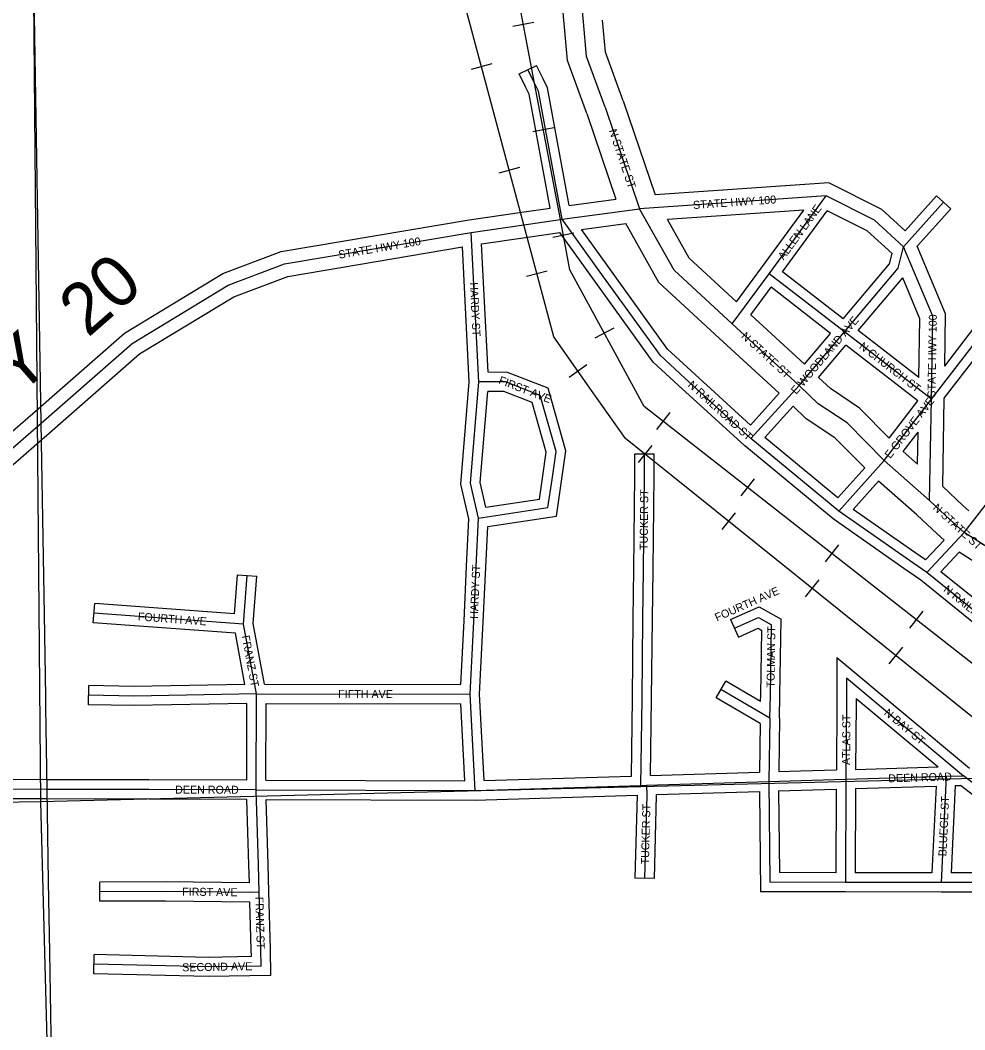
# Model space of a CAD drawing. Extents: x 457167 to 656239, y 1787309 to 1969297.
# Drawn here: x 569552 to 572503, y 1865532 to 1868685 of the extents above; entities that cross this region are included whole.
import ezdxf

# ---------------------------------------------------------------- set-up
doc = ezdxf.new("R2010")
doc.units = 0
for name, color, linetype in [('Level 1', 7, 'Continuous'), ('Level 13', 7, 'Continuous'), ('Level 14', 7, 'Continuous'), ('Level 22', 7, 'Continuous'), ('Level 23', 7, 'Continuous'), ('Level 28', 7, 'Continuous'), ('Level 31', 7, 'Continuous'), ('Level 32', 7, 'Continuous'), ('Level 34', 7, 'Continuous'), ('Level 37', 7, 'Continuous'), ('Level 8', 7, 'Continuous')]:
    doc.layers.add(name, color=color, linetype=linetype)

msp = doc.modelspace()

# ---------------------------------------------------------------- linework, layer by layer
at = {"layer": 'Level 1'}
for p, q in [((569570.685, 1871499.854), (569615.691, 1866243.956)), ((574895.419, 1866376.943), (569615.691, 1866243.956)), ((569615.691, 1866243.956), (564358.417, 1866182.997)), ((569615.691, 1866243.956), (569751.086, 1861047.655))]:
    msp.add_line(p, q, dxfattribs=at)
at = {"layer": 'Level 13'}
for p, q in [((571311.617, 1868679.365), (571287.401, 1868943.418)), ((571379.106, 1868413.031), (571486.576, 1868096.061)), ((571594.65, 1867903.816), (571486.576, 1868096.061)), ((571776.29, 1867736.496), (571594.65, 1867903.816)), ((571985.241, 1867544.389), (571776.29, 1867736.496)), ((572393.025, 1867184.926), (572251.381, 1867310.336)), ((572457.488, 1867124.781), (572393.025, 1867184.926)), ((572500.994, 1867084.684), (572457.488, 1867124.781)), ((572817.176, 1866883.612), (572500.994, 1867084.684))]:
    msp.add_line(p, q, dxfattribs=at)
for points in [[(571379.106, 1868413.031), (571321.236, 1868571.707), (571311.617, 1868679.365)], [(572251.381, 1867310.336), (572135.176, 1867427.324), (572045.306, 1867487.276), (571985.241, 1867544.389)]]:
    msp.add_lwpolyline(points, dxfattribs=at)
at = {"layer": 'Level 14'}
for p, q in [((571251.867, 1868673.884), (571227.65, 1868937.937)), ((571435.711, 1868432.946), (571535.205, 1868139.5)), ((571322.503, 1868393.115), (571412.934, 1868126.401)), ((571547.006, 1867866.126), (571443.721, 1868049.854)), ((571642.295, 1867941.506), (571574.549, 1868062.015)), ((571789.897, 1867805.54), (571642.296, 1867941.506)), ((571735.637, 1867692.366), (571547.006, 1867866.126)), ((572001.992, 1867610.495), (571834.307, 1867764.662)), ((571922.916, 1867520.183), (571735.68, 1867692.326)), ((572354.991, 1867298.74), (572310.564, 1867338.075)), ((572352.666, 1867140.521), (572233.771, 1867245.786)), ((572498.152, 1867168.901), (572433.795, 1867228.949)), ((572515.666, 1867152.761), (572498.152, 1867168.901)), ((572416.556, 1867080.91), (572352.666, 1867140.52)), ((572437.886, 1867061.249), (572416.825, 1867080.661)), ((572753.867, 1866852.766), (572484.986, 1867023.758))]:
    msp.add_line(p, q, dxfattribs=at)
for points in [[(571322.503, 1868393.116), (571262.172, 1868558.536), (571251.855, 1868674.025)], [(571435.711, 1868432.945), (571380.299, 1868584.879), (571371.38, 1868684.705)], [(572266.956, 1867379.796), (572173.493, 1867473.889), (572082.904, 1867534.321), (572045.901, 1867569.505)], [(572190.067, 1867286.921), (572096.86, 1867380.759), (572007.706, 1867440.231), (571966.739, 1867479.186)]]:
    msp.add_lwpolyline(points, dxfattribs=at)
at = {"layer": 'Level 22'}
for p, q in [((572070.271, 1868136.193), (571486.576, 1868096.061)), ((571244.976, 1868063.157), (571486.576, 1868096.061)), ((570961.354, 1868022.351), (571125.289, 1868045.976)), ((571125.289, 1868045.976), (571239.565, 1868062.442)), ((571239.565, 1868062.442), (571244.976, 1868063.157)), ((572393.025, 1867184.926), (572398.511, 1867501.639)), ((568581.391, 1866522.794), (569617.736, 1867426.909))]:
    msp.add_line(p, q, dxfattribs=at)
for points in [[(572311.756, 1867977.103), (572220.298, 1868060.582), (572070.271, 1868136.193)], [(569617.736, 1867426.909), (569901.528, 1867674.976), (570202.348, 1867857.552), (570377.52, 1867923.693), (570961.354, 1868022.351)], [(572398.511, 1867501.639), (572402.913, 1867760.172), (572311.756, 1867977.103)]]:
    msp.add_lwpolyline(points, dxfattribs=at)
at = {"layer": 'Level 23'}
for p, q in [((572078.476, 1868176.851), (571535.206, 1868139.499)), ((571119.585, 1868085.568), (571207.957, 1868098.301)), ((571267.445, 1868106.586), (571412.935, 1868126.401)), ((570955.168, 1868061.873), (571119.583, 1868085.568)), ((572000.041, 1868091.269), (571574.549, 1868062.015)), ((571305.166, 1868030.983), (571443.72, 1868049.854)), ((570993.216, 1867986.528), (571130.995, 1868006.384)), ((571130.993, 1868006.384), (571237.83, 1868021.778)), ((572433.795, 1867228.949), (572438.568, 1867504.474)), ((568567.431, 1866563.696), (569591.441, 1867457.051)), ((568607.686, 1866492.651), (569644.033, 1867396.766)), ((572354.991, 1867298.74), (572356.711, 1867398.078))]:
    msp.add_line(p, q, dxfattribs=at)
for points in [[(572316.315, 1868027.099), (572243.207, 1868093.831), (572078.476, 1868176.851)], [(572275.451, 1867956.083), (572197.389, 1868027.334), (572073.423, 1868089.811)], [(569591.411, 1867457.026), (569877.811, 1867707.374), (570184.757, 1867893.667), (570367.024, 1867962.486), (570955.168, 1868061.874)], [(569644.062, 1867396.792), (569925.245, 1867642.579), (570219.939, 1867821.436), (570388.016, 1867884.899), (570933.617, 1867977.096)], [(572440.28, 1867605.007), (572443.051, 1867767.908), (572354.163, 1867979.439)], [(572359.661, 1867569.536), (572362.775, 1867752.436), (572308.942, 1867880.546)]]:
    msp.add_lwpolyline(points, dxfattribs=at)
at = {"layer": 'Level 31'}
for p, q in [((571158.757, 1868488.078), (571137.852, 1868530.308)), ((571891.84, 1867893.326), (572070.271, 1868136.193)), ((572311.756, 1867977.103), (572436.491, 1868116.095)), ((571361.076, 1867902.166), (571244.976, 1868063.157)), ((570985.104, 1867555.391), (570961.354, 1868022.351)), ((571776.29, 1867736.496), (571891.84, 1867893.326)), ((572126.908, 1867711.341), (571891.84, 1867893.326)), ((572398.511, 1867501.639), (572588.406, 1867748.119)), ((571985.241, 1867544.389), (572126.908, 1867711.341)), ((572398.511, 1867501.639), (572126.908, 1867711.341)), ((571834.984, 1867378.185), (571628.252, 1867567.38)), ((570959.239, 1867238.725), (570985.104, 1867555.391)), ((571834.984, 1867378.185), (571985.241, 1867544.389)), ((572251.381, 1867310.336), (572398.511, 1867501.639)), ((572109.415, 1867152.111), (571834.984, 1867378.185)), ((571502.181, 1867263.305), (571502.653, 1867330.94)), ((572109.415, 1867152.111), (572251.381, 1867310.336)), ((572500.994, 1867084.684), (572664.719, 1867296.679)), ((571498.966, 1866969.496), (571502.181, 1867263.305)), ((570983.812, 1867130.306), (570959.239, 1867238.725)), ((572329.595, 1866997.797), (572109.415, 1867152.111)), ((570976.781, 1866978.323), (570983.812, 1867130.306)), ((572383.925, 1866959.857), (572500.994, 1867084.684)), ((572383.925, 1866959.857), (572329.595, 1866997.797)), ((570968.753, 1866807.796), (570976.781, 1866978.323)), ((571497.341, 1866814.956), (571498.966, 1866969.496)), ((570249.543, 1866798.905), (570261.033, 1866951.241)), ((572683.466, 1866717.368), (572383.925, 1866959.857)), ((570249.543, 1866798.905), (569782.786, 1866833.439)), ((570957.411, 1866580.188), (570968.753, 1866807.796)), ((571494.549, 1866566.963), (571497.341, 1866814.956)), ((570290.411, 1866581.721), (570249.543, 1866798.905)), ((571895.54, 1866577.69), (571898.901, 1866796.953)), ((572133.376, 1866630.971), (572133.197, 1866551.698)), ((572133.376, 1866630.971), (572498.968, 1866325.786)), ((571894.104, 1866505.694), (571741.238, 1866594.766)), ((569906.93, 1866574.607), (569765.962, 1866577.48)), ((570290.411, 1866581.721), (569906.93, 1866574.607)), ((570289.718, 1866281.725), (570290.411, 1866581.721)), ((570290.411, 1866581.721), (570957.411, 1866580.188)), ((570973.271, 1866279.791), (570957.411, 1866580.188)), ((571491.066, 1866295.336), (571494.549, 1866566.963)), ((571894.104, 1866505.694), (571895.54, 1866577.69)), ((572133.197, 1866551.698), (572131.706, 1866314.612)), ((571894.104, 1866505.694), (571891.109, 1866307.52)), ((571508.571, 1866296.024), (571891.109, 1866307.52)), ((571891.109, 1866307.52), (571990.403, 1866310.568)), ((571891.109, 1866307.52), (571894.216, 1865993.334)), ((571990.403, 1866310.568), (572131.706, 1866314.612)), ((572131.706, 1866314.612), (572129.706, 1865992.801)), ((572131.706, 1866314.612), (572444.547, 1866324.09)), ((572444.547, 1866324.09), (572428.844, 1865992.491)), ((572444.547, 1866324.09), (572498.968, 1866325.786)), ((572841.107, 1866060.656), (572498.968, 1866325.786)), ((569636.396, 1866283.237), (569470.181, 1866283.63)), ((569953.669, 1866282.501), (569636.396, 1866283.237)), ((570289.718, 1866281.725), (569953.669, 1866282.501)), ((570289.718, 1866281.725), (570973.271, 1866279.791)), ((570296.497, 1866047.892), (570289.718, 1866281.725)), ((570973.271, 1866279.791), (571491.066, 1866295.336)), ((571491.066, 1866295.336), (571508.571, 1866296.024)), ((570298.845, 1865962.069), (570296.497, 1866047.892)), ((572129.706, 1865992.801), (571894.216, 1865993.334)), ((572428.844, 1865992.491), (572129.706, 1865992.801)), ((572841.59, 1865991.929), (572428.844, 1865992.491)), ((570005.758, 1865964.565), (569801.132, 1865963.585)), ((570303.842, 1865783.514), (570298.845, 1865962.069)), ((570304.995, 1865731.511), (570303.842, 1865783.514)), ((570139.156, 1865728.676), (569783.104, 1865737.446)), ((570304.995, 1865731.511), (570139.156, 1865728.676))]:
    msp.add_line(p, q, dxfattribs=at)
for points in [[(571244.976, 1868063.157), (571170.793, 1868463.687), (571158.757, 1868488.078)], [(572126.908, 1867711.341), (572294.739, 1867910.233), (572311.756, 1867977.103)], [(571628.252, 1867567.38), (571552.039, 1867637.371), (571361.076, 1867902.166)], [(571176.576, 1867513.136), (571068.477, 1867555.2), (570985.104, 1867555.391)], [(571213.524, 1867250.144), (571226.136, 1867338.115), (571176.576, 1867513.136)], [(570983.812, 1867130.306), (571200.596, 1867162.901), (571213.524, 1867250.144)], [(571783.361, 1866786.306), (571858.538, 1866819.59), (571898.901, 1866796.953)], [(571508.571, 1866296.024), (571509.134, 1866263.66), (571502.5, 1866005.495)], [(570298.845, 1865962.069), (570268.611, 1865961.412), (570005.758, 1865964.565)]]:
    msp.add_lwpolyline(points, dxfattribs=at)
at = {"layer": 'Level 32'}
for p, q in [((571110.966, 1868516.998), (571164.739, 1868543.616)), ((571185.644, 1868501.387), (571164.739, 1868543.616)), ((571131.871, 1868474.769), (571110.966, 1868516.998)), ((572316.315, 1868027.099), (572414.163, 1868136.131)), ((572414.163, 1868136.131), (572458.819, 1868096.057)), ((572354.163, 1867979.44), (572458.819, 1868096.057)), ((571867.664, 1867911.087), (572000.041, 1868091.268)), ((571933.339, 1867899.138), (572073.423, 1868089.811)), ((571336.743, 1867884.618), (571237.83, 1868021.778)), ((571385.41, 1867919.714), (571305.166, 1868030.983)), ((570955.042, 1867555.851), (570933.617, 1867977.096)), ((571013.622, 1867585.326), (570993.216, 1867986.529)), ((571789.897, 1867805.54), (571867.688, 1867911.121)), ((572122.53, 1867752.67), (571933.339, 1867899.137)), ((572170.044, 1867715.939), (572308.942, 1867880.546)), ((571834.306, 1867764.662), (571897.769, 1867850.795)), ((572083.732, 1867706.826), (571897.769, 1867850.795)), ((572440.28, 1867605.007), (572564.641, 1867766.428)), ((572438.568, 1867504.473), (572612.172, 1867729.81)), ((572001.991, 1867610.495), (572083.732, 1867706.826)), ((572359.661, 1867569.536), (572170.044, 1867715.938)), ((572045.901, 1867569.506), (572131.25, 1867670.086)), ((572356.476, 1867496.192), (572131.249, 1867670.086)), ((571832.971, 1867420.692), (571648.507, 1867589.511)), ((570928.965, 1867236.581), (570955.042, 1867555.851)), ((571815.306, 1867355.526), (571607.999, 1867545.248)), ((570989.516, 1867240.868), (571012.75, 1867525.326)), ((571832.972, 1867420.692), (571922.917, 1867520.183)), ((571878.304, 1867381.366), (571966.739, 1867479.186)), ((572266.956, 1867379.796), (572356.476, 1867496.192)), ((572106.293, 1867193.551), (571878.305, 1867381.366)), ((572310.564, 1867338.075), (572356.711, 1867398.078)), ((572091.241, 1867128.213), (571815.306, 1867355.525)), ((571472.181, 1867263.513), (571472.654, 1867331.148)), ((571472.654, 1867331.148), (571532.654, 1867330.73)), ((571532.182, 1867263.095), (571532.654, 1867330.73)), ((572106.292, 1867193.552), (572190.067, 1867286.921)), ((571468.969, 1866969.824), (571472.183, 1867263.632)), ((571528.966, 1866969.167), (571532.181, 1867262.976)), ((572154.341, 1867157.258), (572233.772, 1867245.786)), ((570953.656, 1867127.634), (570928.965, 1867236.58)), ((571006.911, 1867164.116), (570989.516, 1867240.868)), ((572346.771, 1867022.394), (572154.341, 1867157.258)), ((570946.813, 1866979.709), (570953.656, 1867127.635)), ((572312.377, 1866973.23), (572091.241, 1867128.212)), ((571006.75, 1866976.936), (571012.643, 1867104.301)), ((572379.81, 1866999.323), (572437.887, 1867061.249)), ((572379.81, 1866999.323), (572346.771, 1867022.394)), ((572427.882, 1866962.871), (572484.986, 1867023.758)), ((570938.786, 1866809.207), (570946.814, 1866979.733)), ((570998.721, 1866806.386), (571006.749, 1866976.911)), ((571467.342, 1866815.27), (571468.968, 1866969.811)), ((571527.341, 1866814.64), (571528.966, 1866969.181)), ((572365.876, 1866935.87), (572312.419, 1866973.201)), ((572678.951, 1866759.621), (572427.882, 1866962.871)), ((570221.881, 1866831.033), (570231.118, 1866953.497)), ((570231.118, 1866953.497), (570290.95, 1866948.984)), ((570279.756, 1866800.577), (570290.95, 1866948.984)), ((572664.341, 1866694.255), (572365.876, 1866935.87)), ((569780.573, 1866803.521), (569785, 1866863.357)), ((570221.881, 1866831.032), (569785, 1866863.357)), ((570224.326, 1866770.687), (569780.573, 1866803.521)), ((570928.872, 1866610.253), (570938.79, 1866809.289)), ((570987.452, 1866580.232), (570998.717, 1866806.304)), ((571464.551, 1866567.301), (571467.343, 1866815.292)), ((571524.548, 1866566.625), (571527.34, 1866814.617)), ((571771.216, 1866813.738), (571795.506, 1866758.874)), ((571925.537, 1866577.23), (571929.173, 1866814.371)), ((570315.304, 1866611.663), (570279.756, 1866800.577)), ((571865.546, 1866578.288), (571868.631, 1866779.533)), ((570254.364, 1866611.057), (570224.326, 1866770.687)), ((572103.521, 1866694.971), (572103.197, 1866551.766)), ((572103.521, 1866694.971), (572517.776, 1866349.165)), ((571726.135, 1866568.846), (571756.342, 1866620.687)), ((571865.127, 1866557.299), (571756.342, 1866620.687)), ((569765.351, 1866547.486), (569766.574, 1866607.474)), ((569906.958, 1866604.613), (569766.574, 1866607.474)), ((570254.364, 1866611.056), (569906.958, 1866604.612)), ((570315.304, 1866611.663), (570928.873, 1866610.253)), ((570260.34, 1866551.156), (569906.903, 1866544.601)), ((570259.788, 1866311.794), (570260.34, 1866551.156)), ((570319.788, 1866311.64), (570320.342, 1866551.651)), ((570320.342, 1866551.651), (570928.951, 1866550.252)), ((571001.684, 1866310.656), (570987.452, 1866580.232)), ((571461.437, 1866324.46), (571464.551, 1866567.347)), ((571521.47, 1866326.425), (571524.548, 1866566.578)), ((571863.843, 1866488.605), (571726.135, 1866568.846)), ((571865.128, 1866557.3), (571865.546, 1866578.288)), ((571924.101, 1866505.24), (571925.535, 1866577.091)), ((572103.197, 1866551.886), (572101.889, 1866343.771)), ((572163.197, 1866551.51), (572161.903, 1866345.541)), ((572163.232, 1866566.967), (572163.197, 1866551.631)), ((572163.233, 1866566.967), (572419.152, 1866353.334)), ((569906.903, 1866544.601), (569765.351, 1866547.486)), ((570941.641, 1866309.88), (570928.951, 1866550.252)), ((571863.843, 1866488.605), (571861.546, 1866336.645)), ((571924.101, 1866505.24), (571921.581, 1866338.469)), ((571521.47, 1866326.425), (571861.546, 1866336.644)), ((571921.581, 1866338.469), (571989.483, 1866340.554)), ((571989.546, 1866340.556), (572101.89, 1866343.771)), ((572161.903, 1866345.541), (572419.152, 1866353.334)), ((569636.466, 1866313.237), (569511.154, 1866313.528)), ((569953.739, 1866312.501), (569636.465, 1866313.237)), ((570259.787, 1866311.793), (569953.739, 1866312.501)), ((570319.788, 1866311.639), (570941.641, 1866309.88)), ((571001.685, 1866310.656), (571461.438, 1866324.46)), ((571539.083, 1866266.926), (571861.413, 1866276.613)), ((571861.413, 1866276.612), (571864.51, 1865963.4)), ((571921.4, 1866278.434), (571991.325, 1866280.581)), ((571921.4, 1866278.434), (571923.922, 1866023.266)), ((571991.262, 1866280.579), (572101.515, 1866283.734)), ((572101.515, 1866283.734), (572099.893, 1866022.869)), ((572161.527, 1866285.501), (572159.895, 1866022.77)), ((572161.527, 1866285.501), (572413.047, 1866293.121)), ((572413.048, 1866293.121), (572400.233, 1866022.521)), ((572473.203, 1866294.966), (572460.297, 1866022.448)), ((572473.203, 1866294.967), (572489.121, 1866295.462)), ((572811.211, 1866045.87), (572489.121, 1866295.463)), ((569636.326, 1866253.237), (569480.076, 1866253.6)), ((569953.6, 1866252.501), (569636.326, 1866253.237)), ((570260.574, 1866251.791), (569953.6, 1866252.501)), ((570266.51, 1866047.022), (570260.574, 1866251.791)), ((570320.604, 1866251.636), (570973.68, 1866249.789)), ((570326.485, 1866048.761), (570320.604, 1866251.636)), ((570973.68, 1866249.789), (571479.156, 1866264.966)), ((571479.156, 1866264.966), (571472.509, 1866006.266)), ((570268.031, 1865991.421), (570266.508, 1866047.071)), ((570328.834, 1865962.889), (570326.486, 1866048.711)), ((572099.893, 1866022.868), (571923.922, 1866023.266)), ((572400.232, 1866022.521), (572159.894, 1866022.769)), ((572811.378, 1866021.969), (572460.297, 1866022.448)), ((570005.875, 1865994.566), (569800.99, 1865993.584)), ((569801.276, 1865933.584), (569800.99, 1865993.584)), ((570268.031, 1865991.421), (570005.875, 1865994.566)), ((571532.49, 1866004.725), (571472.509, 1866006.266)), ((570333.831, 1865784.353), (570328.833, 1865962.908)), ((572129.639, 1865962.801), (571864.51, 1865963.4)), ((572428.813, 1865962.491), (572129.676, 1865962.801)), ((572871.803, 1865961.887), (572428.803, 1865962.491)), ((570005.691, 1865934.563), (569801.276, 1865933.584)), ((570273.854, 1865782.675), (570269.691, 1865931.427)), ((569782.366, 1865707.454), (569783.842, 1865767.437)), ((570139.292, 1865758.682), (569783.842, 1865767.437)), ((570274.334, 1865760.991), (570273.849, 1865782.849)), ((570335.657, 1865702.03), (570333.836, 1865784.179)), ((570274.335, 1865760.991), (570139.292, 1865758.682)), ((570139.031, 1865698.669), (569782.366, 1865707.454)), ((570335.656, 1865702.031), (570139.031, 1865698.669))]:
    msp.add_line(p, q, dxfattribs=at)
for points in [[(571207.957, 1868098.301), (571142.051, 1868454.138), (571131.854, 1868474.803)], [(571267.445, 1868106.586), (571199.536, 1868473.237), (571185.66, 1868501.354)], [(572122.53, 1867752.67), (572267.366, 1867924.312), (572275.45, 1867956.083)], [(571648.546, 1867589.476), (571574.583, 1867657.399), (571385.409, 1867919.715)], [(571607.96, 1867545.283), (571529.495, 1867617.342), (571336.743, 1867884.618)], [(571201.373, 1867535.678), (571074.142, 1867585.187), (571013.622, 1867585.325)], [(571243.221, 1867245.886), (571256.736, 1867340.161), (571201.373, 1867535.678)], [(571151.779, 1867490.591), (571062.812, 1867525.213), (571012.75, 1867525.326)], [(571183.827, 1867254.401), (571195.536, 1867336.068), (571151.779, 1867490.591)], [(571006.911, 1867164.115), (571174.175, 1867189.266), (571183.848, 1867254.541)], [(571012.643, 1867104.302), (571227.018, 1867136.536), (571243.201, 1867245.746)], [(571771.216, 1866813.738), (571860.12, 1866853.1), (571929.172, 1866814.371)], [(571795.506, 1866758.874), (571856.956, 1866786.08), (571868.631, 1866779.533)], [(571539.083, 1866266.926), (571539.141, 1866263.535), (571532.49, 1866004.725)], [(570269.69, 1865931.427), (570268.756, 1865931.407), (570005.691, 1865934.563)]]:
    msp.add_lwpolyline(points, dxfattribs=at)
at = {"layer": 'Level 37'}
for p, q in [((571157.119, 1868677.292), (571090.958, 1868664.736)), ((571025.933, 1868548.426), (570960.871, 1868531.047)), ((571219.566, 1868348.311), (571153.404, 1868335.75)), ((571112.346, 1868224.909), (571047.285, 1868207.531)), ((571282.013, 1868019.319), (571215.85, 1868006.772)), ((571198.758, 1867901.391), (571133.696, 1867884.014)), ((571406.621, 1867723.669), (571347.498, 1867691.43)), ((571322.109, 1867608.275), (571267.109, 1867569.416)), ((571581.104, 1867459.51), (571539.566, 1867406.504)), ((571524.741, 1867356.385), (571482.503, 1867303.935)), ((571844.676, 1867252.968), (571803.14, 1867199.961)), ((571785.696, 1867146.616), (571743.528, 1867094.111)), ((572108.251, 1867046.427), (572066.712, 1866993.42)), ((572046.78, 1866936.936), (572004.611, 1866884.43)), ((572371.823, 1866839.886), (572330.286, 1866786.878)), ((572307.889, 1866727.301), (572265.733, 1866674.786))]:
    msp.add_line(p, q, dxfattribs=at)
for points in [[(573273.651, 1866090.601), (573107.051, 1866159.335), (573036.151, 1866188.583), (572807.237, 1866283.276), (572109.036, 1866843.751), (571590.957, 1867259.83), (571502.653, 1867330.94), (571442.938, 1867379.075), (571337.311, 1867528.406), (571218.681, 1867696.311), (571125.289, 1868045.976), (570889.606, 1868928.327), (570822.406, 1869179.753), (570418.272, 1870691.219), (570243.943, 1870983.619), (569919.906, 1871342.912), (568713.123, 1872196.271), (563862.541, 1875551.618), (562796.998, 1876288.824), (562639.826, 1876412.128), (562231.185, 1876732.066), (560701.821, 1878317.053), (560697.551, 1878322.202)], [(573273.651, 1866090.601), (573134.826, 1866198.909), (573077.962, 1866243.762), (571501.718, 1867478.94), (571269.436, 1867904.921), (571239.565, 1868062.442), (571158.757, 1868488.078), (571074.179, 1868933.724), (570567.377, 1871602.871), (570537.826, 1871758.211), (569677.096, 1877204.181), (569610.387, 1878202.152), (569624.745, 1878220.301), (569619.136, 1878270.496), (569615.058, 1878295.232), (569614.549, 1878298.363)]]:
    msp.add_lwpolyline(points, dxfattribs=at)
at = {"layer": 'Level 8'}
msp.add_lwpolyline([(569722.917, 1861044.269), (569688.899, 1863064.298), (569644.873, 1865775.338), (569640.871, 1865995.341), (569636.869, 1866283.346), (569631.866, 1866539.35), (569631.866, 1866573.35), (569627.864, 1866829.354), (569617.858, 1867427.362), (569593.845, 1868889.384), (570889.866, 1868928.401), (571073.869, 1868933.403), (571287.873, 1868943.406), (571851.882, 1868954.413), (571813.871, 1870180.431), (571153.86, 1870155.422), (571085.851, 1870906.433), (571060.851, 1870981.433), (571052.848, 1871223.437)], dxfattribs=at)

# ---------------------------------------------------------------- texts
at = {"layer": 'Level 28'}
for s, p in [('20', (569763.531, 1867691.535)), ('HWY', (569278.566, 1867275.445))]:
    msp.add_text(s, height=160, rotation=41.1011, dxfattribs=at).set_placement(p)
at = {"layer": 'Level 34'}
for s, rotation, p in [('N STATE ST', 288.728856, (571390.664, 1868340.018)), ('STATE HWY 100', 3.932397, (571654.851, 1868095.103)), ('ALLEN LANE', 53.69515, (571937.143, 1867933.877)), ('STATE HWY 100', 9.590758, (570548.538, 1867939.916)), ('HARDY ST', 272.911169, (570956.811, 1867865.616)), ('E WOODLAND AVE', 49.6832, (571976.348, 1867514.591)), ('STATE HWY 100', 89.0242, (572411.086, 1867505.987)), ('N STATE ST', 317.404239, (571802.748, 1867695.193)), ('N CHURCH ST', 322.328036, (572170.558, 1867661.848)), ('FIRST AVE', 338.736517, (571044.466, 1867551.132)), ('N RAILROAD ST', 317.535419, (571636.049, 1867543.301)), ('E GROVE AVE', 52.435722, (572270.049, 1867314.106)), ('TUCKER ST', 89.372567, (571512.131, 1867030.284)), ('N STATE ST', 317.334133, (572401.291, 1867159.578)), ('HARDY ST', 87.304056, (570981.609, 1866815.077)), ('FOURTH AVE', 23.880425, (571728.804, 1866806.999)), ('N RAILROAD ST', 321.007867, (572434.031, 1866903.213)), ('FOURTH AVE', 355.767792, (569919.127, 1866810.818)), ('TOLMAN ST', 89.121283, (571908.393, 1866600.683)), ('FRANZ ST', 280.656236, (570243.801, 1866761.824)), ('FIFTH AVE', 359.86765, (570545.457, 1866568.636)), ('N BAY ST', 320.145272, (572248.682, 1866518.435)), ('ATLAS ST', 89.639272, (572144.485, 1866358.905)), ('DEEN ROAD', 1.784147, (572263.969, 1866304.932)), ('DEEN ROAD', 359.866878, (570036.153, 1866269.811)), ('TUCKER ST', 88.527439, (571516.102, 1866048.3)), ('BLUEGE ST', 87.288144, (572445.203, 1866073.699)), ('FIRST AVE', 359.312092, (570058.142, 1865951.436)), ('FRANZ ST', 271.602714, (570286.748, 1865947.531)), ('SECOND AVE', 0.978808, (570058.478, 1865714.796))]:
    msp.add_text(s, height=25, rotation=rotation, dxfattribs=at).set_placement(p)

doc.saveas('drawing.dxf')
